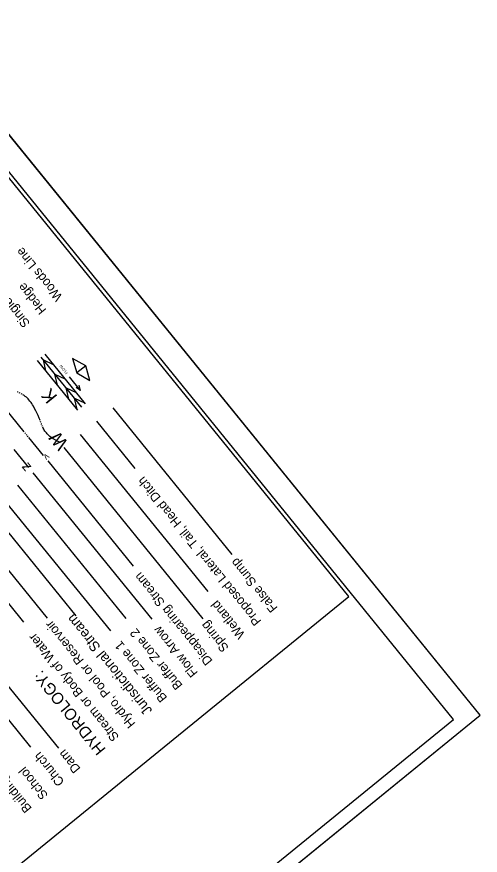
# Model space of a CAD drawing. Extents: x 2596486 to 2602076, y 851390 to 856110.
# Drawn here: x 2600253 to 2600696, y 854669 to 855469 of the extents above; entities that cross this region are included whole.
import ezdxf

# ---------------------------------------------------------------- set-up
doc = ezdxf.new("R2010")
doc.units = 0
for name, color, linetype in [('Sheet Cutting Line CELL', 7, 'Continuous'), ('Sheet Plot Border Inside CELL', 7, 'Continuous'), ('Sheet Plot Border Outside CELL', 7, 'Continuous'), ('Sheet Symbology CELL', 7, 'Continuous')]:
    doc.layers.add(name, color=color, linetype=linetype)

msp = doc.modelspace()

# ---------------------------------------------------------------- linework, layer by layer
at = {"layer": 'Sheet Cutting Line CELL'}
for p, q in [((2600696, 854802.71), (2599633.88, 856109.52)), ((2599842.38, 854108.93), (2600696, 854802.71))]:
    msp.add_line(p, q, dxfattribs=at)
at = {"layer": 'Sheet Plot Border Inside CELL'}
msp.add_lwpolyline([(2600670.38, 854798.64), (2599619.29, 856091.87), (2598800.52, 855426.4), (2599851.6, 854133.17)], close=True, dxfattribs=at)
at = {"layer": 'Sheet Plot Border Outside CELL'}
msp.add_lwpolyline([(2600696, 854802.71), (2599633.88, 856109.52), (2598780.26, 855415.74), (2599842.38, 854108.93)], close=True, dxfattribs=at)
at = {"layer": 'Sheet Symbology CELL'}
for p, q in [((2600318.68, 855099.72), (2600280.2, 855147.07)), ((2600311.35, 855093.76), (2600272.87, 855141.1)), ((2600315.24, 855096.58), (2600276.59, 855144.13)), ((2600280.88, 855131.24), (2600278.55, 855141.72)), ((2600278.55, 855141.72), (2600288.05, 855137.4)), ((2600319.02, 855136.15), (2600306.33, 855143)), ((2600306.33, 855143), (2600310.44, 855129.18)), ((2600319.02, 855136.15), (2600310.44, 855129.18)), ((2600310.44, 855129.18), (2600323.1, 855121.97)), ((2600323.1, 855121.97), (2600319.02, 855136.15)), ((2600292.07, 855117.48), (2600289.6, 855128.13)), ((2600289.6, 855128.13), (2600299.18, 855123.71)), ((2600314.13, 855112.45), (2600303.63, 855125.37)), ((2600302.76, 855104.32), (2600300.31, 855114.94)), ((2600300.31, 855114.94), (2600309.9, 855110.52)), ((2600314.13, 855112.45), (2600310.06, 855115.32)), ((2600314.13, 855112.45), (2600312.62, 855117.41)), ((2600256.41, 855109.8), (2600255.54, 855110.27)), ((2600258.16, 855108.82), (2600257.28, 855109.3)), ((2600310.78, 855094.46), (2600308.33, 855105.08)), ((2600308.33, 855105.08), (2600317.94, 855100.63)), ((2600260.29, 855072.94), (2600241.37, 855096.22)), ((2600344.79, 855095.82), (2600458.49, 854955.93)), ((2600276.2, 855081.99), (2600275.85, 855082.93)), ((2600329.27, 855083.21), (2600365.96, 855038.06)), ((2600261.55, 855071.39), (2600260.92, 855072.17)), ((2600262.81, 855069.84), (2600262.18, 855070.62)), ((2600264.07, 855068.29), (2600263.44, 855069.06)), ((2600278.6, 855050.42), (2600264.71, 855067.51)), ((2600313.75, 855070.59), (2600435.61, 854920.66)), ((2600298.22, 855057.98), (2600430.97, 854894.65)), ((2600264.54, 855038.99), (2600250.65, 855056.08)), ((2600282.7, 855045.37), (2600364.39, 854944.86)), ((2600268.65, 855033.94), (2600382.07, 854894.38)), ((2600254, 855022.04), (2600357.28, 854894.96)), ((2600239.36, 855010.13), (2600342.64, 854883.06)), ((2600226.46, 854999.65), (2600309.47, 854897.53)), ((2600208.93, 854985.4), (2600282.34, 854895.08)), ((2600193.41, 854972.79), (2600259.63, 854891.31)), ((2600150.74, 854946.02), (2600292.91, 854771.08)), ((2600135.22, 854933.4), (2600266.22, 854772.21))]:
    msp.add_line(p, q, dxfattribs=at)
msp.add_lwpolyline([(2598810.38, 855418.31), (2599756.45, 854254.29), (2600570.48, 854915.9), (2599624.41, 856079.92)], close=True, dxfattribs=at)
for points in [[(2600254.65, 855110.74), (2600254.46, 855110.84), (2600253.76, 855111.19)], [(2600275.5, 855083.87), (2600275.23, 855084.63), (2600274.66, 855085.98), (2600273.52, 855088.51), (2600272.64, 855090.41), (2600271.27, 855093.21), (2600269.83, 855095.98), (2600268.99, 855097.49), (2600268.22, 855098.8), (2600267.5, 855099.92), (2600266.85, 855100.89), (2600266.25, 855101.7), (2600265.7, 855102.42), (2600264.7, 855103.61), (2600263.91, 855104.46), (2600263.28, 855105.08), (2600262.32, 855105.96), (2600261.31, 855106.77), (2600260.5, 855107.35), (2600259.77, 855107.85), (2600259.01, 855108.31)], [(2600276.88, 855080.12), (2600276.73, 855080.52), (2600276.54, 855081.06)], [(2600277.62, 855078.26), (2600277.43, 855078.71), (2600277.24, 855079.18)], [(2600294.11, 855063.04), (2600291.4, 855064.5), (2600288.67, 855065.95), (2600288.01, 855066.33), (2600286.87, 855067.03), (2600286.05, 855067.63), (2600284.87, 855068.55), (2600283.73, 855069.53), (2600282.84, 855070.39), (2600282.08, 855071.19), (2600281.45, 855071.92), (2600280.91, 855072.58), (2600280.04, 855073.79), (2600279.43, 855074.73), (2600279, 855075.44), (2600278.41, 855076.55), (2600278.03, 855077.34)]]:
    msp.add_lwpolyline(points, dxfattribs=at)

# ---------------------------------------------------------------- texts
for s, height, rotation, p in [('Woods Line', 8.75, 129.10281, (2600297.39, 855202.03)), ('Single Shrub', 8.75, 129.10281, (2600266.35, 855176.8)), ('Hedge', 8.75, 129.10281, (2600281.87, 855189.41)), ('FLOW', 2.593, 129.10281, (2600302.2, 855129.28)), ('K', 12.75, 129.10281, (2600292.58, 855106.74)), ('W', 12.75, 129.10281, (2600303.08, 855062.12)), ('v', 6.6, 218.86195, (2600281.5, 855052.78)), ('z', 10, 309.10283, (2600257.5, 855039.73)), ('Proposed Lateral, Tail, Head Ditch', 8.75, 129.10281, (2600487.27, 854892.39)), ('False Sump', 8.75, 129.10281, (2600502.79, 854905)), ('Disappearing Stream', 8.75, 129.10281, (2600440.71, 854854.54)), ('Wetland', 8.75, 129.10281, (2600471.75, 854879.77)), ('Jurisdictional Stream', 9.646, 129.10281, (2600383.08, 854807.27)), ('Hydro, Pool or Reservoir', 8.75, 129.10281, (2600366.94, 854794.58)), ('Spring', 8.75, 129.10281, (2600456.23, 854867.16)), ('Buffer Zone 2', 8.75, 129.10281, (2600412.01, 854831.22)), ('Flow Arrow', 8.75, 129.10281, (2600426.65, 854843.12)), ('Stream or Body of Water', 8.75, 129.10281, (2600351.41, 854781.97)), ('Buffer Zone 1', 8.75, 129.10281, (2600397.36, 854819.31)), ('HYDROLOGY:', 11, 129.10281, (2600338.72, 854770.18)), ('Dam', 8.75, 129.10281, (2600314.53, 854751.64)), ('Church', 8.75, 129.10281, (2600299.15, 854739.15)), ('School', 8.75, 129.10281, (2600283.5, 854726.4)), ('Building', 8.75, 129.10281, (2600267.97, 854713.79))]:
    msp.add_text(s, height=height, rotation=rotation, dxfattribs=at).set_placement(p)

doc.saveas('drawing.dxf')
